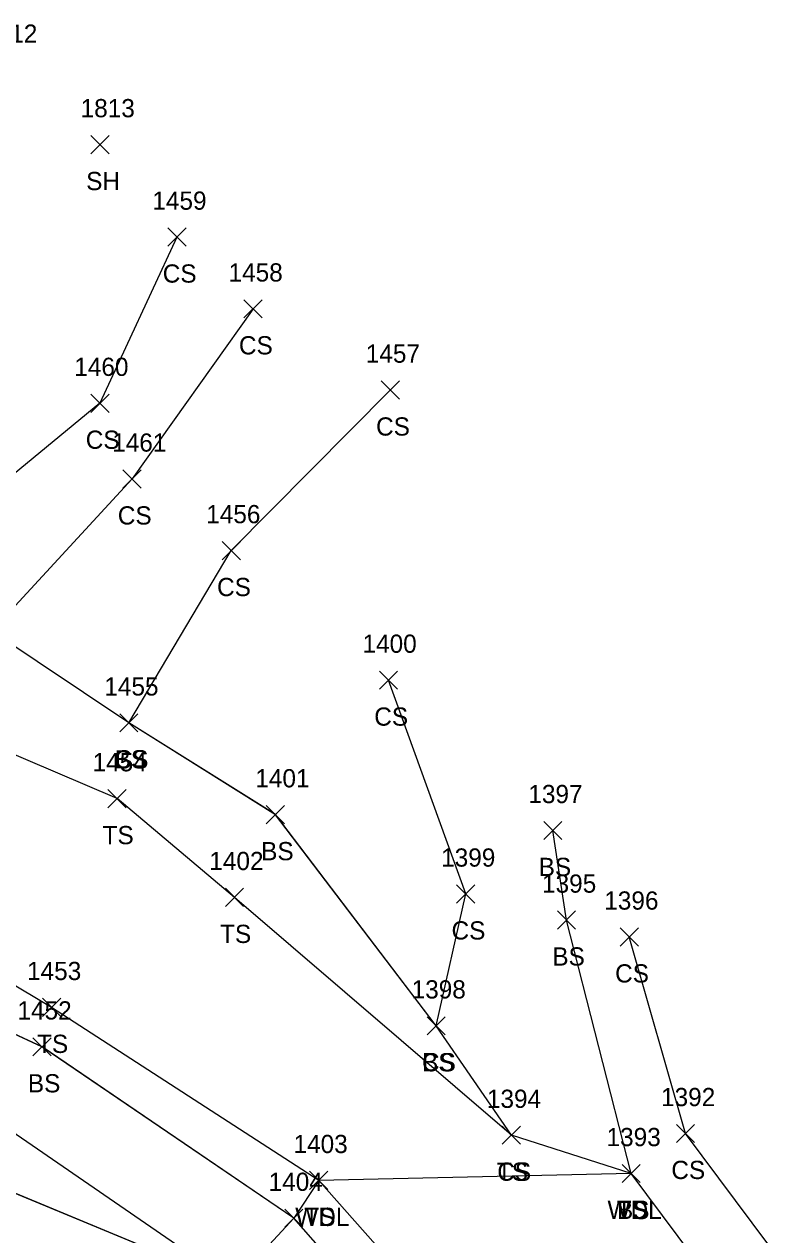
# Model space of a CAD drawing. Extents: x 1415642 to 1422021, y 544543 to 547232.
# Drawn here: x 1416280.8 to 1416364, y 546804.9 to 546937.8 of the extents above; entities that cross this region are included whole.
import ezdxf

# ---------------------------------------------------------------- set-up
doc = ezdxf.new("R2010")
doc.units = 0
for name, color, linetype in [('L_A', 7, 'Continuous'), ('L_I', 7, 'Continuous'), ('L_TIC', 7, 'Continuous'), ('LAWA', 7, 'Continuous'), ('LELB', 7, 'Continuous')]:
    doc.layers.add(name, color=color, linetype=linetype)

msp = doc.modelspace()

# ---------------------------------------------------------------- linework, layer by layer
at = {"layer": 'L_TIC'}
for points in [[(1416288.07, 546923.56), (1416290.07, 546925.56)], [(1416290.07, 546923.56), (1416288.07, 546925.56)], [(1416296.51, 546913.41), (1416298.51, 546915.41)], [(1416298.51, 546913.41), (1416296.51, 546915.41)], [(1416304.86, 546905.53), (1416306.86, 546907.53)], [(1416306.86, 546905.53), (1416304.86, 546907.53)], [(1416319.92, 546896.62), (1416321.92, 546898.62)], [(1416321.92, 546896.62), (1416319.92, 546898.62)], [(1416288.06, 546895.17), (1416290.06, 546897.17)], [(1416290.06, 546895.17), (1416288.06, 546897.17)], [(1416291.58, 546886.86), (1416293.58, 546888.86)], [(1416293.58, 546886.86), (1416291.58, 546888.86)], [(1416302.47, 546879), (1416304.47, 546881)], [(1416304.47, 546879), (1416302.47, 546881)], [(1416319.72, 546864.78), (1416321.72, 546866.78)], [(1416321.72, 546864.78), (1416319.72, 546866.78)], [(1416291.23, 546860.09), (1416293.23, 546862.09)], [(1416293.23, 546860.09), (1416291.23, 546862.09)], [(1416291.23, 546860.09), (1416293.23, 546862.09)], [(1416293.23, 546860.09), (1416291.23, 546862.09)], [(1416289.94, 546851.77), (1416291.94, 546853.77)], [(1416291.94, 546851.77), (1416289.94, 546853.77)], [(1416307.31, 546850.01), (1416309.31, 546852.01)], [(1416309.31, 546850.01), (1416307.31, 546852.01)], [(1416337.76, 546848.28), (1416339.76, 546850.28)], [(1416339.76, 546848.28), (1416337.76, 546850.28)], [(1416302.83, 546840.93), (1416304.83, 546842.93)], [(1416304.83, 546840.93), (1416302.83, 546842.93)], [(1416328.2, 546841.31), (1416330.2, 546843.31)], [(1416330.2, 546841.31), (1416328.2, 546843.31)], [(1416339.26, 546838.45), (1416341.26, 546840.45)], [(1416341.26, 546838.45), (1416339.26, 546840.45)], [(1416346.15, 546836.59), (1416348.15, 546838.59)], [(1416348.15, 546836.59), (1416346.15, 546838.59)], [(1416282.75, 546828.86), (1416284.75, 546830.86)], [(1416284.75, 546828.86), (1416282.75, 546830.86)], [(1416324.96, 546826.84), (1416326.96, 546828.84)], [(1416326.96, 546826.84), (1416324.96, 546828.84)], [(1416324.96, 546826.84), (1416326.96, 546828.84)], [(1416326.96, 546826.84), (1416324.96, 546828.84)], [(1416281.7, 546824.53), (1416283.7, 546826.53)], [(1416283.7, 546824.53), (1416281.7, 546826.53)], [(1416333.21, 546814.83), (1416335.21, 546816.83)], [(1416335.21, 546814.83), (1416333.21, 546816.83)], [(1416333.21, 546814.83), (1416335.21, 546816.83)], [(1416335.21, 546814.83), (1416333.21, 546816.83)], [(1416352.32, 546815.02), (1416354.32, 546817.02)], [(1416354.32, 546815.02), (1416352.32, 546817.02)], [(1416346.35, 546810.63), (1416348.35, 546812.63)], [(1416348.35, 546810.63), (1416346.35, 546812.63)], [(1416346.35, 546810.63), (1416348.35, 546812.63)], [(1416348.35, 546810.63), (1416346.35, 546812.63)], [(1416346.35, 546810.63), (1416348.35, 546812.63)], [(1416348.35, 546810.63), (1416346.35, 546812.63)], [(1416312.07, 546809.87), (1416314.07, 546811.87)], [(1416314.07, 546809.87), (1416312.07, 546811.87)], [(1416312.07, 546809.87), (1416314.07, 546811.87)], [(1416314.07, 546809.87), (1416312.07, 546811.87)], [(1416309.34, 546805.72), (1416311.34, 546807.72)], [(1416311.34, 546805.72), (1416309.34, 546807.72)], [(1416309.34, 546805.72), (1416311.34, 546807.72)], [(1416311.34, 546805.72), (1416309.34, 546807.72)]]:
    msp.add_lwpolyline(points, dxfattribs=at)
at = {"layer": 'LAWA'}
for points in [[(1416347.35, 546811.63), (1416313.07, 546810.87), (1416310.34, 546806.72), (1416303.68, 546799.52), (1416268.96, 546813.92)], [(1416347.34, 546811.63), (1416313.07, 546810.87), (1416310.34, 546806.72), (1416303.68, 546799.52), (1416268.96, 546813.91)]]:
    msp.add_lwpolyline(points, dxfattribs=at)
at = {"layer": 'LELB'}
for points in [[(1416297.51, 546914.41), (1416289.06, 546896.17), (1416268.52, 546879.28)], [(1416297.51, 546914.41), (1416289.06, 546896.17), (1416268.52, 546879.28)], [(1416305.86, 546906.53), (1416292.58, 546887.86), (1416277.16, 546871.16)], [(1416305.86, 546906.53), (1416292.58, 546887.86), (1416277.16, 546871.16)], [(1416292.23, 546861.09), (1416303.47, 546880), (1416320.92, 546897.62)], [(1416292.23, 546861.1), (1416303.47, 546880), (1416320.92, 546897.62)], [(1416325.96, 546827.84), (1416308.31, 546851.01), (1416292.23, 546861.09), (1416277.16, 546871.16), (1416268.52, 546879.28), (1416238.86, 546893.5)], [(1416325.96, 546827.84), (1416308.31, 546851.02), (1416292.23, 546861.1), (1416277.16, 546871.16), (1416268.52, 546879.28), (1416238.86, 546893.5)], [(1416396.19, 546650.28), (1416389.93, 546664.1), (1416375.33, 546699.79), (1416360.48, 546732.7), (1416344.12, 546775.76), (1416313.07, 546810.87), (1416283.75, 546829.86), (1416246.42, 546852.16), (1416221.38, 546861.32), (1416210.74, 546868.88), (1416211.4, 546870.4), (1416221.96, 546889.07)], [(1416396.19, 546650.28), (1416389.93, 546664.1), (1416375.33, 546699.79), (1416360.49, 546732.7), (1416344.12, 546775.76), (1416313.07, 546810.87), (1416283.75, 546829.86), (1416246.42, 546852.16), (1416221.38, 546861.32), (1416210.75, 546868.87), (1416211.4, 546870.4), (1416221.97, 546889.07)], [(1416347.35, 546811.63), (1416334.21, 546815.83), (1416303.83, 546841.93), (1416290.94, 546852.77), (1416257.83, 546866.92), (1416232.61, 546882.55), (1416221.96, 546889.07)], [(1416347.34, 546811.63), (1416334.22, 546815.83), (1416303.83, 546841.93), (1416290.94, 546852.77), (1416257.83, 546866.92), (1416232.62, 546882.55), (1416221.97, 546889.07)], [(1416334.21, 546815.83), (1416325.96, 546827.84), (1416329.2, 546842.31), (1416320.72, 546865.78)], [(1416334.22, 546815.83), (1416325.96, 546827.84), (1416329.2, 546842.31), (1416320.72, 546865.78)], [(1416399.91, 546654.53), (1416394.35, 546666.38), (1416375.33, 546699.79), (1416357.07, 546731.49), (1416339.46, 546773.58), (1416310.34, 546806.72), (1416282.7, 546825.53), (1416242.81, 546844.04), (1416212.63, 546849.89), (1416203.83, 546852.66), (1416197.94, 546856.2), (1416209.64, 546861.99)], [(1416399.91, 546654.53), (1416394.35, 546666.37), (1416375.33, 546699.79), (1416357.08, 546731.49), (1416339.45, 546773.58), (1416310.34, 546806.72), (1416282.71, 546825.53), (1416242.81, 546844.04), (1416212.62, 546849.89), (1416203.83, 546852.66), (1416197.94, 546856.21), (1416209.64, 546861.99)], [(1416487.57, 546505.93), (1416480.71, 546505.12), (1416469.86, 546502.72), (1416462.76, 546510.55), (1416442.83, 546541.19), (1416430.44, 546560.72), (1416424.35, 546585.18), (1416398.34, 546624.28), (1416389.66, 546643.26), (1416377.3, 546653.03), (1416344.54, 546704.05), (1416343.42, 546724.77), (1416329.35, 546768.04), (1416303.68, 546799.52), (1416274.8, 546819.39), (1416239.26, 546839.41), (1416210.61, 546845.46), (1416203.47, 546849.21), (1416195, 546854.49)], [(1416487.57, 546505.93), (1416480.71, 546505.12), (1416469.86, 546502.72), (1416462.76, 546510.55), (1416442.83, 546541.19), (1416430.44, 546560.72), (1416424.35, 546585.18), (1416398.34, 546624.28), (1416389.66, 546643.27), (1416377.3, 546653.03), (1416344.54, 546704.05), (1416343.42, 546724.76), (1416329.35, 546768.04), (1416303.68, 546799.52), (1416274.8, 546819.4), (1416239.26, 546839.41), (1416210.61, 546845.46), (1416203.48, 546849.21), (1416195, 546854.49)], [(1416488.29, 546504.83), (1416488.12, 546506.46), (1416480.5, 546522.11), (1416462.74, 546551.59), (1416447.84, 546594.51), (1416422.44, 546641.16), (1416410.18, 546676.27), (1416393.07, 546713.79), (1416378.8, 546749.63), (1416367.97, 546783.97), (1416347.35, 546811.63), (1416340.26, 546839.45), (1416338.76, 546849.28)], [(1416488.29, 546504.83), (1416488.12, 546506.46), (1416480.5, 546522.11), (1416462.74, 546551.59), (1416447.84, 546594.51), (1416422.44, 546641.16), (1416410.17, 546676.27), (1416393.07, 546713.79), (1416378.8, 546749.63), (1416367.97, 546783.97), (1416347.34, 546811.63), (1416340.26, 546839.45), (1416338.76, 546849.28)], [(1416449.42, 546597.09), (1416431.29, 546645.7), (1416419.63, 546678.87), (1416400.37, 546718.89), (1416388.41, 546748.65), (1416375.25, 546786.59), (1416353.32, 546816.02), (1416347.15, 546837.59)], [(1416449.42, 546597.08), (1416431.29, 546645.7), (1416419.63, 546678.87), (1416400.37, 546718.89), (1416388.42, 546748.65), (1416375.25, 546786.59), (1416353.33, 546816.03), (1416347.15, 546837.59)]]:
    msp.add_lwpolyline(points, dxfattribs=at)

# ---------------------------------------------------------------- texts
at = {"layer": 'L_A'}
for s, p in [('SH', (1416287.55, 546919.56)), ('CS', (1416295.95, 546909.41)), ('CS', (1416304.31, 546901.53)), ('CS', (1416319.36, 546892.62)), ('CS', (1416287.5, 546891.17)), ('CS', (1416291.02, 546882.86)), ('CS', (1416301.91, 546875)), ('CS', (1416319.16, 546860.78)), ('CS', (1416290.67, 546856.09)), ('BS', (1416290.67, 546856.09)), ('TS', (1416289.35, 546847.77)), ('BS', (1416306.75, 546846.01)), ('BS', (1416337.2, 546844.28)), ('TS', (1416302.24, 546836.93)), ('CS', (1416327.64, 546837.31)), ('BS', (1416338.7, 546834.45)), ('CS', (1416345.59, 546832.59)), ('TS', (1416282.16, 546824.86)), ('CS', (1416324.4, 546822.84)), ('BS', (1416324.4, 546822.84)), ('BS', (1416281.15, 546820.53)), ('TS', (1416332.62, 546810.83)), ('CS', (1416332.66, 546810.83)), ('CS', (1416351.76, 546811.02)), ('WDL', (1416344.76, 546806.63)), ('TS', (1416345.76, 546806.63)), ('BS', (1416345.79, 546806.63)), ('WDL', (1416310.49, 546805.87)), ('TS', (1416311.48, 546805.87))]:
    msp.add_text(s, height=2, dxfattribs=at).set_placement(p)
at = {"layer": 'L_I'}
for s, p in [('1812', (1416276.24, 546935.74)), ('1813', (1416286.94, 546927.56)), ('1459', (1416294.81, 546917.41)), ('1458', (1416303.17, 546909.53)), ('1457', (1416318.23, 546900.62)), ('1460', (1416286.24, 546899.17)), ('1461', (1416290.4, 546890.86)), ('1456', (1416300.72, 546883)), ('1400', (1416317.87, 546868.78)), ('1455', (1416289.54, 546864.09)), ('1455', (1416289.54, 546864.09)), ('1454', (1416288.25, 546855.77)), ('1401', (1416306.11, 546854.01)), ('1397', (1416336.07, 546852.28)), ('1402', (1416301.06, 546844.93)), ('1399', (1416326.5, 546845.31)), ('1395', (1416337.57, 546842.45)), ('1396', (1416344.4, 546840.59)), ('1453', (1416281.06, 546832.86)), ('1398', (1416323.26, 546830.84)), ('1398', (1416323.26, 546830.84)), ('1452', (1416280.01, 546828.53)), ('1394', (1416331.52, 546818.83)), ('1394', (1416331.52, 546818.83)), ('1392', (1416350.63, 546819.02)), ('1393', (1416344.65, 546814.63)), ('1393', (1416344.65, 546814.63)), ('1393', (1416344.65, 546814.63)), ('1403', (1416310.3, 546813.87)), ('1403', (1416310.3, 546813.87)), ('1404', (1416307.57, 546809.72)), ('1404', (1416307.57, 546809.72))]:
    msp.add_text(s, height=2, dxfattribs=at).set_placement(p)

doc.saveas('drawing.dxf')
